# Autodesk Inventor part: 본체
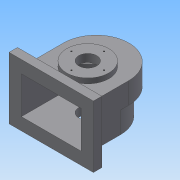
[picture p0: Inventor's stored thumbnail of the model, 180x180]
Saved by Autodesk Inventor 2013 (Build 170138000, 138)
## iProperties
Created: 2017-11
Part Number: 본체
Material: 일반
Document SubType Name: Modeling
Designer: Administrator
Density: 1 g/cm^3
Author: Administrator
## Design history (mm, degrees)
sketch "스케치1"
  geometry: L1 (-58, 0)-(-58, -80); L2 (58, 0)-(58, -80); L3 (-58, -80)-(58, -80); L4 (-75, -65)-(75, -65); L5 (75, -65)-(75, -80); L6 (75, -80)-(-75, -80); L7 (-75, -80)-(-75, -65); A1 r 58 centre (0, 0) between (58, 0) and (-58, 0); 4 further points
  constraints: 14 end point, 4 parallel, 3 midpoint, 2 coincident, 2 perpendicular, 2 point on circle, 2 tangent, 1 centre point, 1 horizontal, 1 vertical, 1 vertical alignment
  dimensions: "d0" = 116 diameter of A1; "d1" = 80 distance of L2.start L2.end; "d9" = 150 distance of L5.end L6.end; "d10" = 15 distance of L6.end L4.start
extrude "돌출1" new body sketch "스케치1" distance "d2" = 38; taper "d3" = 0 deg
sketch "스케치2"
  geometry: L1 (-58, 0)-(-58, -80) reference; L2 (-58, -80)-(58, -80) reference; L3 (58, -80)-(58, 0) reference; L4 (58, -15)-(58, -80); L5 (-58, -80)-(-58, -15); A1 r 58 centre (0, 0) between (58, 0) and (-58, 0) reference; A2 r 58 centre (0, -15) between (58, -15) and (-58, -15)
  constraints: 4 end point, 2 point on circle, 2 point on line, 1 centre point, 1 collinear, 1 vertical alignment
  dimensions: "d4" = 116 diameter of A2; "d6" = 65 distance from line of L2 A2.centre
extrude "돌출2" join sketch "스케치2" distance "d7" = 38; taper "d8" = 0 deg
feature "쉘1" dims "d15" = 5
extrude "돌출3" join sketch "스케치1" distance "d11" = 17; taper "d13" = 0 deg; dims "d12" = 93, "d14" = 0
sketch "스케치3"
  geometry: L1 (128, -88)-(128, -22) reference; L2 (128, -22)-(22, -22) reference; L3 (22, -22)-(22, -88) reference; L4 (22, -88)-(128, -88) reference; 1 further point
extrude "돌출4" cut sketch "스케치3" distance "d16" = 15; taper "d17" = 0 deg
sketch "스케치4"
  geometry: L1 (-75, -80)-(75, -80) reference; C1 r 37.5 at (0, -15); A1 r 58 centre (0, 0) between (58, 0) and (-58, 0) reference
  constraints: 1 centre point, 1 vertical alignment
  dimensions: "d18" = 75 diameter of C1; "d20" = 65 distance from line of L1 C1.centre
extrude "돌출5" join sketch "스케치4" distance "d21" = 9; taper "d22" = 0 deg
sketch "스케치5"
  geometry: L1 (-75, -80)-(75, -80) reference; C1 r 31 at (0, -15); 1 further point
  constraints: 1 centre point, 1 vertical alignment
  dimensions: "d23" = 62 diameter of C1; "d25" = 65 distance from line of C1.centre L1
extrude "돌출6" join sketch "스케치5" distance "d26" = 10; taper "d27" = 0 deg
hole "구멍1" diameter "d30" = 32; stored, may be unused: countersink angle "d34" = 90 deg, drill point angle "d36" = 118 deg; dims "d28" = 10, "d29" = 10, "d31" = 6, "d32" = 4, "d33" = 2, "d35" = 8
sketch "스케치6"
  geometry: C1 r 16 at (0, 0) reference; 2 further points
  constraints: 1 vertical alignment
  dimensions: "d37" = 29 distance of C1.centre point (0, 29)
hole "구멍2" sketch "스케치6" at (0, 29) diameter "d38" = 2.459; stored, may be unused: countersink angle "d42" = 90 deg, drill point angle "d44" = 118 deg; dims "d39" = 6, "d40" = 4, "d41" = 2, "d43" = 8
sketch "스케치7"
  geometry: C1 r 16 at (0, 0) reference; 2 further points
  constraints: 1 vertical alignment
  dimensions: "d48" = 26 distance of C1.centre point (0, 26)
hole "구멍3" sketch "스케치7" at (0, 26) diameter "d49" = 2.459; stored, may be unused: countersink angle "d53" = 90 deg, drill point angle "d55" = 118 deg; dims "d50" = 6, "d51" = 4, "d52" = 2, "d54" = 8
node "솔리드1"
pattern_circular "원형 패턴1" dims angle "d46" = 360 deg
pattern_circular "원형 패턴2" dims angle "d57" = 360 deg
